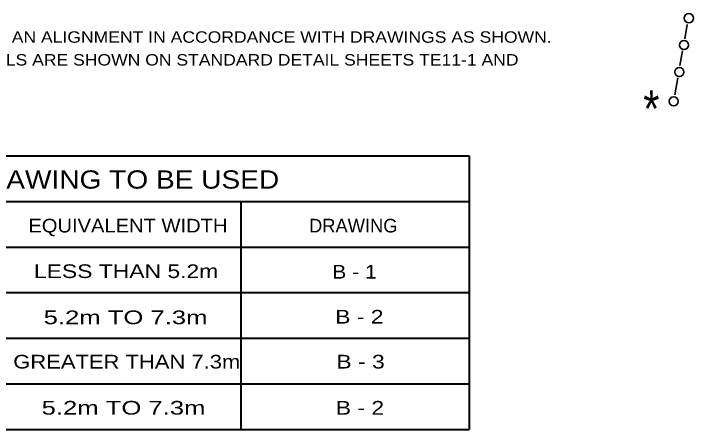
# Model space of a CAD drawing. Extents: x -1843 to -987, y 1073 to 1617.
# Drawn here: x -1659.1 to -1480.3, y 1238.3 to 1347.8 of the extents above; entities that cross this region are included whole.
import ezdxf
from ezdxf.enums import TextEntityAlignment as Align

# ---------------------------------------------------------------- set-up
doc = ezdxf.new("R2010")
doc.units = 0
doc.header["$LTSCALE"] = 1.2
doc.layers.add('1', color=7, linetype='Continuous', lineweight=53)

msp = doc.modelspace()

# ---------------------------------------------------------------- linework, layer by layer
at = {"layer": '1', "lineweight": 35}
for p, q in [((-1482.57, 1341.087), (-1481.893, 1344.924)), ((-1483.809, 1334.061), (-1483.115, 1337.996)), ((-1485.15, 1326.34), (-1484.355, 1330.844))]:
    msp.add_line(p, q, dxfattribs=at)
at = {"layer": '1', "lineweight": 40}
for p, q in [((-1719.272, 1310.333), (-1539.272, 1310.333)), ((-1539.272, 1310.333), (-1539.272, 1238.333)), ((-1719.272, 1298.333), (-1539.272, 1298.333)), ((-1599.272, 1298.333), (-1599.272, 1238.333)), ((-1719.272, 1286.333), (-1539.272, 1286.333)), ((-1719.272, 1274.333), (-1539.272, 1274.333)), ((-1719.272, 1262.333), (-1539.272, 1262.333)), ((-1719.272, 1250.333), (-1539.272, 1250.333)), ((-1719.272, 1238.333), (-1539.272, 1238.333))]:
    msp.add_line(p, q, dxfattribs=at)
at = {"layer": '1', "lineweight": 35}
for centre in [(-1481.48, 1346.562), (-1482.73, 1339.471), (-1483.98, 1332.38), (-1485.465, 1324.667)]:
    msp.add_circle(centre, 1.2, dxfattribs=at)

# ---------------------------------------------------------------- texts
at = {"layer": '1', "width": 1.15}
for s, p in [('DELINEATORS SHALL BE PLACED IN AN ALIGNMENT IN ACCORDANCE WITH DRAWINGS AS SHOWN.', (-1742.363, 1340.094)), ('THE DELINEATOR MOUNTING DETAILS ARE SHOWN ON STANDARD DETAIL SHEETS TE11-1 AND', (-1742.363, 1334.094))]:
    msp.add_text(s, height=3, dxfattribs=at).set_placement(p)
at = {"layer": '1'}
for s, height, width, p in [('*', 9.6, 0.85, (-1491.334, 1317.923)), ('DRAWING TO BE USED', 4.8, 1.15, (-1630.434, 1301.701)), ('EQUIVALENT WIDTH', 3.6, 1.1, (-1628.997, 1290.156)), ('LESS THAN 5.2m', 3.6, 1.25, (-1629.476, 1278.171)), ('B - 1', 3.6, 1.15, (-1569.411, 1278.011)), ('5.2m TO 7.3m', 3.6, 1.4, (-1629.621, 1266.027)), ('B - 2', 3.6, 1.25, (-1568.133, 1266.186)), ('GREATER THAN 7.3m', 3.6, 1.2, (-1629.302, 1254.361)), ('B - 3', 3.6, 1.25, (-1567.814, 1254.361)), ('5.2m TO 7.3m', 3.6, 1.4, (-1630.154, 1242.228)), ('B - 2', 3.6, 1.25, (-1567.973, 1242.217))]:
    msp.add_text(s, height=height, dxfattribs=dict(at, width=width)).set_placement(p, align=Align.CENTER)
msp.add_text('DRAWING', height=3.6, dxfattribs=at).set_placement((-1569.731, 1290.156), align=Align.CENTER)

doc.saveas('drawing.dxf')
